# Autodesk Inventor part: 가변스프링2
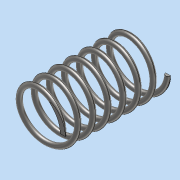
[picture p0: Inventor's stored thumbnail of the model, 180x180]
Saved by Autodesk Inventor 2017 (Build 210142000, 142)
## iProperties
Part Number: 가변스프링2
Material: 스테인레스 스틸
Document SubType Name: Modeling
Designer: MRC
Density: 8 g/cm^3
Appearance: 반연마
Mass: 10.9393 g
Surface Area: 27.6351 cm^2
Volume: 1.36741 cm^3
Author: MRC
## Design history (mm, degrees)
sketch "스케치1"
  geometry: L1 (0, 0)-(10, 0); L2 (10, 0)-(10, 41.411); L3 (10, 41.411)-(0, 41.411); L4 (0, 41.411)-(0, 0); C1 r 1 at (10, 0)
  constraints: 8 end point, 2 parallel, 1 centre point, 1 coincident, 1 horizontal, 1 perpendicular
  dimensions: "d0" = 41.4112 distance of L3.end L1.start (derived); "d1" = 20 diameter of L2 L4; "d2" = 2 diameter of C1
feature "코일1" sketch "스케치1" pitch "d3" = 10; turns "d5" = 7; dims "d4" = 41.4112 (= d0), "d6" = 0, angle "d7" = 90 deg, angle "d8" = 90 deg, "d9" = 0, "d10" = 0
sketch "스케치2"
  geometry: L1 (-25, 41.411)-(25, 41.411); L2 (25, 41.411)-(25, 0); L3 (25, 0)-(-25, 0); L4 (-25, 0)-(-25, 41.411); L5 (0, 41.411)-(0, 0) reference; 2 further points
  constraints: 8 end point, 2 midpoint, 2 parallel, 1 coincident, 1 horizontal, 1 perpendicular
  dimensions: "d11" = 50 distance of L1.start L1.end
extrude "돌출1" sketch "스케치2" stored distance "d12" = 0; taper "d13" = 0 deg
node "솔리드1"
